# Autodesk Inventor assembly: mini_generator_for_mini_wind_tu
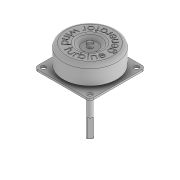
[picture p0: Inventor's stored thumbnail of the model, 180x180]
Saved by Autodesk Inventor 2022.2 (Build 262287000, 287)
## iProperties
Created: 2025-01
Part Number: mini_generator_for_mini_wind_tu
Document SubType Name: Assembly
Designer: 18907419
Sending System: Pro/ENGINEER  TM  Release 20.0
Author: 18907419
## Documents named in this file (3)
- C:\Users\18907419\Desktop\mini\Creo\mini_generator_for_mini_wind_tu.iam
- C:\Users\18907419\Desktop\mini\Creo\ROTOR.iam
- C:\Users\18907419\Desktop\mini\Creo\STATOR.iam
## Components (2 placed, 2 different names)
1. ROTOR [sub-assembly]
2. STATOR [sub-assembly]
